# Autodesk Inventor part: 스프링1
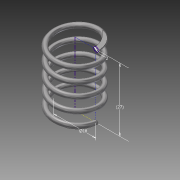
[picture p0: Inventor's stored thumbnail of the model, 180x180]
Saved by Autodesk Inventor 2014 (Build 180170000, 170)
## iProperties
Created: 2016-10
Part Number: 스프링1
Material: Steel, Carbon
Document SubType Name: Modeling
Designer: user
Mass: 6.88058 g
Surface Area: 17.7464 cm^2
Volume: 0.87428 cm^3
Density: 7.87 g/cm^3
Appearance: Semi-Polished
Author: user
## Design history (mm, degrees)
sketch "Sketch1"
  geometry: L1 (0, 0)-(-9, 0); L2 (-9, 0)-(-9, -16.67); L3 (-9, -16.67)-(0, -16.67); L4 (0, -16.67)-(0, 0); C1 r 1 at (-9, 0)
  constraints: 8 end point, 2 parallel, 1 centre point, 1 coincident, 1 horizontal, 1 perpendicular
  dimensions: "d0" = 16.66987 distance of L1.end L2.end (derived); "d1" = 2 diameter of C1; "d2" = 18 diameter of L2 L4
coil "Coil1" pitch "d3" = 10; turns "d5" = 5; dims "d4" = 16.66987 (= d0), "d6" = 0, angle "d7" = 90 deg, angle "d8" = 90 deg, "d9" = 0, "d10" = 0
sketch "Sketch2"
  geometry: L1 (10, 0)-(8, 0) reference; L2 (10, 0)-(8, 0) reference; 1 further point
  constraints: 2 horizontal alignment
extrude "Extrusion1" cut sketch "Sketch2" stored distance "d11" = 10; taper "d12" = 0 deg
workplane "Work Plane1"
sketch "Sketch3"
  geometry: L1 (-1, 0)-(1, 0) reference; 1 further point
  constraints: 1 horizontal alignment
extrude "Extrusion2" cut sketch "Sketch3" stored distance "d14" = 10; taper "d15" = 0 deg
body "Solid1"
node "Project Cut Edges1"
node "Project Cut Edges2"
node "Project Cut Edges3"
other parameters: "d13" = 90 deg
